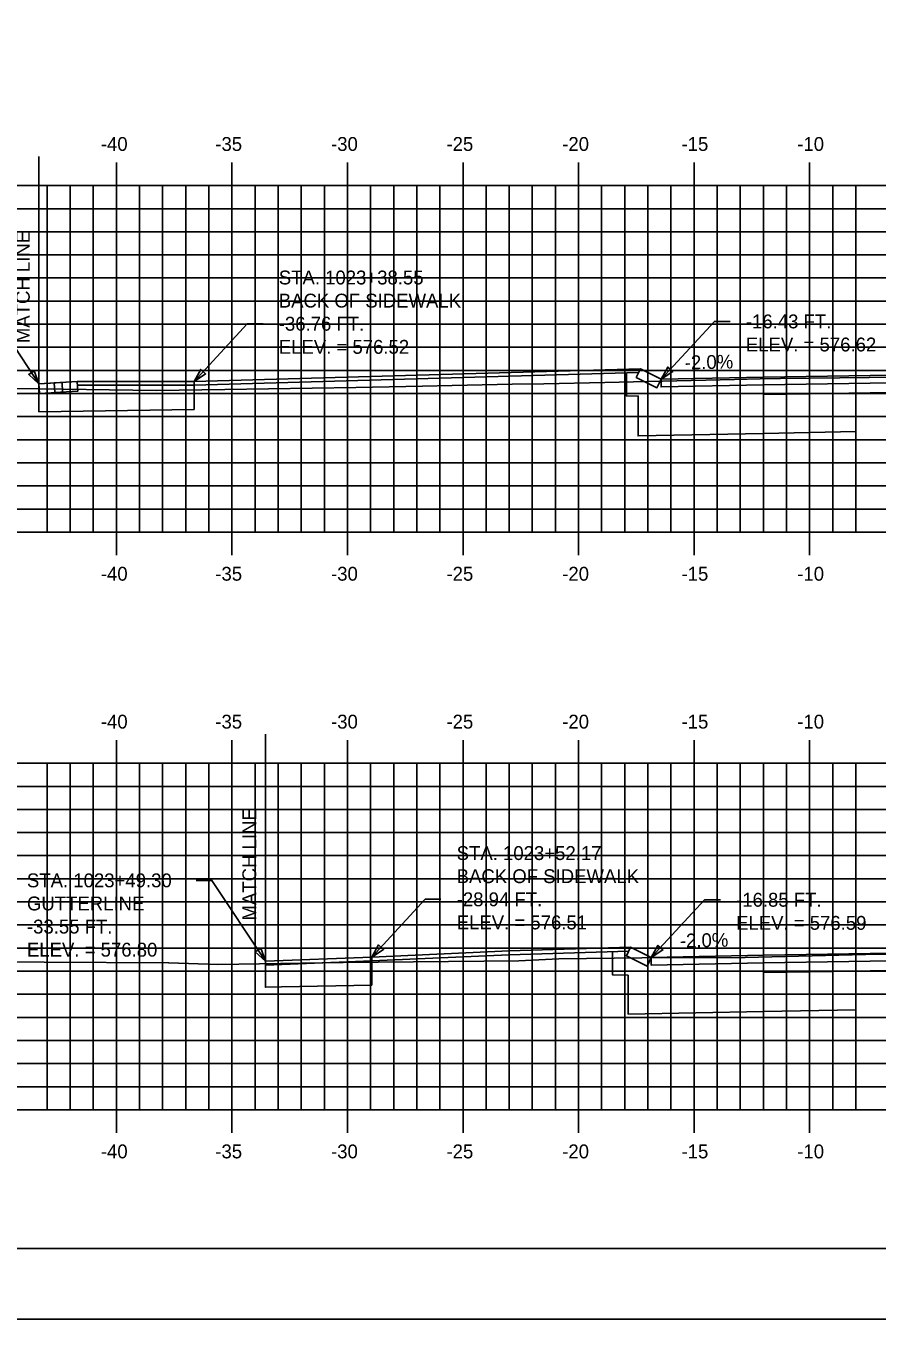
# Model space of a CAD drawing. Extents: x 1048565 to 1048735, y 781387 to 781497.
# Drawn here: x 1048604 to 1048640.8, y 781387.3 to 781443.3 of the extents above; entities that cross this region are included whole.
import ezdxf

# ---------------------------------------------------------------- set-up
doc = ezdxf.new("R2010")
doc.units = 0
for name, color, linetype in [('ANNOTATION', 7, 'Continuous'), ('BORDER', 7, 'Continuous'), ('D_Curb_Type_5_Lt', 7, 'Continuous'), ('D_Curb_Type_5_Rt', 7, 'Continuous'), ('D_Roadway_Edge_Shoulder', 7, 'Continuous'), ('D_Roadway_Edge_TW', 7, 'Continuous'), ('D_Roadway_Pavement', 7, 'Continuous'), ('D_Roadway_Sidewalks_Paved', 7, 'Continuous'), ('D_Roadway_SubGrade', 7, 'Continuous'), ('D_Text_Standard', 7, 'Continuous'), ('E_ROW_Line', 7, 'Continuous'), ('H_V ANNOTATION', 7, 'Continuous'), ('MAJOR', 7, 'Continuous'), ('MINOR', 7, 'Continuous'), ('PLOT BOUNDARY', 7, 'Continuous'), ('S_Roadway_Centerline', 7, 'Continuous')]:
    doc.layers.add(name, color=color, linetype=linetype)

msp = doc.modelspace()

# ---------------------------------------------------------------- linework, layer by layer
at = {"layer": 'ANNOTATION'}
for p, q in [((1048604.523, 781427.795), (1048604.523, 781426.585)), ((1048611.235, 781427.895), (1048611.235, 781426.685)), ((1048630.131, 781403.414), (1048624.876, 781403.256)), ((1048624.876, 781403.256), (1048618.935, 781402.985)), ((1048624.876, 781403.089), (1048618.935, 781402.819)), ((1048618.935, 781402.985), (1048618.935, 781401.775)), ((1048630.047, 781403.244), (1048624.876, 781403.089))]:
    msp.add_line(p, q, dxfattribs=at)
at = {"layer": 'BORDER'}
msp.add_lwpolyline([(1048572.876, 781390.375), (1048732.876, 781390.375), (1048732.876, 781495.375), (1048572.876, 781495.375)], close=True, dxfattribs=at)
at = {"layer": 'D_Curb_Type_5_Lt'}
for points in [[(1048630.556, 781428.444), (1048631.451, 781427.996), (1048631.265, 781427.624), (1048630.37, 781428.071)], [(1048630.131, 781403.414), (1048631.026, 781402.966), (1048630.84, 781402.594), (1048629.945, 781403.041)]]:
    msp.add_lwpolyline(points, close=True, dxfattribs=at)
at = {"layer": 'D_Curb_Type_5_Rt'}
for points in [[(1048604.523, 781427.795), (1048605.522, 781427.856), (1048605.547, 781427.44), (1048604.548, 781427.38)], [(1048605.187, 781427.835), (1048606.185, 781427.895), (1048606.21, 781427.48), (1048605.212, 781427.42)]]:
    msp.add_lwpolyline(points, close=True, dxfattribs=at)
at = {"layer": 'D_Roadway_Edge_Shoulder'}
for points in [[(1048635.876, 781428.085), (1048631.451, 781427.996), (1048631.451, 781427.663), (1048635.876, 781427.752)], [(1048635.876, 781403.063), (1048631.026, 781402.966), (1048631.026, 781402.633), (1048635.876, 781402.73)]]:
    msp.add_lwpolyline(points, close=True, dxfattribs=at)
at = {"layer": 'D_Roadway_Edge_TW'}
for points in [[(1048635.876, 781427.752), (1048635.876, 781428.085), (1048647.876, 781428.271), (1048659.876, 781428.3), (1048659.876, 781427.966), (1048647.876, 781427.938)], [(1048635.876, 781402.73), (1048635.876, 781403.063), (1048647.876, 781403.251), (1048659.876, 781403.385), (1048659.876, 781403.052), (1048647.876, 781402.918)]]:
    msp.add_lwpolyline(points, close=True, dxfattribs=at)
at = {"layer": 'D_Roadway_Pavement'}
for points in [[(1048635.876, 781427.335), (1048635.876, 781427.752), (1048647.876, 781427.938), (1048659.876, 781427.966), (1048659.876, 781427.55), (1048647.876, 781427.521)], [(1048635.876, 781402.314), (1048635.876, 781402.73), (1048647.876, 781402.918), (1048659.876, 781403.052), (1048659.876, 781402.636), (1048647.876, 781402.501)]]:
    msp.add_lwpolyline(points, close=True, dxfattribs=at)
at = {"layer": 'D_Roadway_Sidewalks_Paved'}
for p, q in [((1048611.235, 781427.895), (1048630.556, 781428.444)), ((1048630.474, 781428.279), (1048611.235, 781427.733)), ((1048604.523, 781427.795), (1048606.185, 781427.895)), ((1048606.185, 781427.895), (1048611.235, 781427.895)), ((1048611.235, 781427.733), (1048606.195, 781427.733)), ((1048614.327, 781402.805), (1048618.935, 781402.985)), ((1048614.327, 781402.639), (1048618.935, 781402.819))]:
    msp.add_line(p, q, dxfattribs=at)
at = {"layer": 'D_Roadway_SubGrade'}
for p, q in [((1048629.951, 781427.265), (1048629.951, 781428.264)), ((1048629.951, 781427.289), (1048629.951, 781427.265)), ((1048630.451, 781427.279), (1048629.951, 781427.265)), ((1048611.235, 781426.685), (1048604.523, 781426.585))]:
    msp.add_line(p, q, dxfattribs=at)
for points in [[(1048631.451, 781427.663), (1048635.876, 781427.752), (1048635.876, 781427.335), (1048639.876, 781427.397), (1048639.876, 781425.73), (1048635.876, 781425.65), (1048630.451, 781425.542), (1048630.451, 781427.279)], [(1048629.34, 781403.218), (1048629.34, 781402.218), (1048630.026, 781402.205)], [(1048629.34, 781403.218), (1048629.34, 781402.218), (1048630.026, 781402.205)], [(1048614.327, 781402.683), (1048614.327, 781402.639)], [(1048618.935, 781401.775), (1048615.026, 781401.697), (1048614.327, 781401.683), (1048614.327, 781402.683)], [(1048631.026, 781402.633), (1048635.876, 781402.73), (1048635.876, 781402.314), (1048639.876, 781402.376), (1048639.876, 781400.709), (1048635.876, 781400.629), (1048630.026, 781400.512), (1048630.026, 781402.205)]]:
    msp.add_lwpolyline(points, dxfattribs=at)
at = {"layer": 'D_Text_Standard'}
for points in [[(1048604.524, 781427.794), (1048602.206, 781431.294), (1048601.526, 781431.294)], [(1048611.235, 781427.895), (1048613.542, 781430.395), (1048614.222, 781430.395)], [(1048631.451, 781427.996), (1048633.757, 781430.496), (1048634.437, 781430.496)], [(1048614.327, 781402.805), (1048612.01, 781406.305), (1048611.33, 781406.305)], [(1048618.935, 781402.985), (1048621.242, 781405.485), (1048621.922, 781405.485)], [(1048631.026, 781402.966), (1048633.333, 781405.466), (1048634.013, 781405.466)]]:
    msp.add_lwpolyline(points, dxfattribs=at)
for points in [[(1048604.524, 781427.794), (1048604.081, 781428.199), (1048604.324, 781428.359)], [(1048611.235, 781427.895), (1048611.523, 781428.422), (1048611.737, 781428.225)], [(1048631.451, 781427.996), (1048631.739, 781428.523), (1048631.953, 781428.326)], [(1048618.935, 781402.985), (1048619.223, 781403.512), (1048619.437, 781403.315)], [(1048631.026, 781402.966), (1048631.314, 781403.493), (1048631.528, 781403.296)], [(1048614.327, 781402.805), (1048613.884, 781403.21), (1048614.127, 781403.371)]]:
    msp.add_lwpolyline(points, close=True, dxfattribs=at)
at = {"layer": 'E_ROW_Line'}
for p, q in [((1048604.524, 781427.627), (1048604.524, 781437.627)), ((1048614.327, 781402.639), (1048614.327, 781412.639))]:
    msp.add_line(p, q, dxfattribs=at)
at = {"layer": 'MAJOR'}
for p, q in [((1048607.876, 781437.377), (1048607.876, 781436.375)), ((1048612.876, 781437.377), (1048612.876, 781436.375)), ((1048617.876, 781437.377), (1048617.876, 781436.375)), ((1048622.876, 781437.377), (1048622.876, 781436.375)), ((1048627.876, 781437.377), (1048627.876, 781436.375)), ((1048632.876, 781437.377), (1048632.876, 781436.375)), ((1048637.876, 781437.377), (1048637.876, 781436.375)), ((1048577.876, 781436.375), (1048717.876, 781436.375)), ((1048577.876, 781436.375), (1048717.876, 781436.375)), ((1048607.876, 781421.375), (1048607.876, 781436.375)), ((1048612.876, 781421.375), (1048612.876, 781436.375)), ((1048617.876, 781421.375), (1048617.876, 781436.375)), ((1048622.876, 781421.375), (1048622.876, 781436.375)), ((1048627.876, 781421.375), (1048627.876, 781436.375)), ((1048632.876, 781421.375), (1048632.876, 781436.375)), ((1048637.876, 781421.375), (1048637.876, 781436.375)), ((1048577.876, 781431.375), (1048717.876, 781431.375)), ((1048577.876, 781426.375), (1048717.876, 781426.375)), ((1048577.876, 781421.375), (1048717.876, 781421.375)), ((1048577.876, 781421.375), (1048717.876, 781421.375)), ((1048607.876, 781420.373), (1048607.876, 781421.375)), ((1048612.876, 781420.373), (1048612.876, 781421.375)), ((1048617.876, 781420.373), (1048617.876, 781421.375)), ((1048622.876, 781420.373), (1048622.876, 781421.375)), ((1048627.876, 781420.373), (1048627.876, 781421.375)), ((1048632.876, 781420.373), (1048632.876, 781421.375)), ((1048637.876, 781420.373), (1048637.876, 781421.375)), ((1048607.876, 781412.377), (1048607.876, 781411.375)), ((1048612.876, 781412.377), (1048612.876, 781411.375)), ((1048617.876, 781412.377), (1048617.876, 781411.375)), ((1048622.876, 781412.377), (1048622.876, 781411.375)), ((1048627.876, 781412.377), (1048627.876, 781411.375)), ((1048632.876, 781412.377), (1048632.876, 781411.375)), ((1048637.876, 781412.377), (1048637.876, 781411.375)), ((1048577.876, 781411.375), (1048717.876, 781411.375)), ((1048577.876, 781411.375), (1048717.876, 781411.375)), ((1048607.876, 781396.375), (1048607.876, 781411.375)), ((1048612.876, 781396.375), (1048612.876, 781411.375)), ((1048617.876, 781396.375), (1048617.876, 781411.375)), ((1048622.876, 781396.375), (1048622.876, 781411.375)), ((1048627.876, 781396.375), (1048627.876, 781411.375)), ((1048632.876, 781396.375), (1048632.876, 781411.375)), ((1048637.876, 781396.375), (1048637.876, 781411.375)), ((1048577.876, 781406.375), (1048717.876, 781406.375)), ((1048577.876, 781401.375), (1048717.876, 781401.375)), ((1048577.876, 781396.375), (1048717.876, 781396.375)), ((1048577.876, 781396.375), (1048717.876, 781396.375)), ((1048607.876, 781395.373), (1048607.876, 781396.375)), ((1048612.876, 781395.373), (1048612.876, 781396.375)), ((1048617.876, 781395.373), (1048617.876, 781396.375)), ((1048622.876, 781395.373), (1048622.876, 781396.375)), ((1048627.876, 781395.373), (1048627.876, 781396.375)), ((1048632.876, 781395.373), (1048632.876, 781396.375)), ((1048637.876, 781395.373), (1048637.876, 781396.375))]:
    msp.add_line(p, q, dxfattribs=at)
at = {"layer": 'MINOR'}
for p, q in [((1048604.876, 781421.375), (1048604.876, 781436.375)), ((1048605.876, 781421.375), (1048605.876, 781436.375)), ((1048606.876, 781421.375), (1048606.876, 781436.375)), ((1048608.876, 781421.375), (1048608.876, 781436.375)), ((1048609.876, 781421.375), (1048609.876, 781436.375)), ((1048610.876, 781421.375), (1048610.876, 781436.375)), ((1048611.876, 781421.375), (1048611.876, 781436.375)), ((1048613.876, 781421.375), (1048613.876, 781436.375)), ((1048614.876, 781421.375), (1048614.876, 781436.375)), ((1048615.876, 781421.375), (1048615.876, 781436.375)), ((1048616.876, 781421.375), (1048616.876, 781436.375)), ((1048618.876, 781421.375), (1048618.876, 781436.375)), ((1048619.876, 781421.375), (1048619.876, 781436.375)), ((1048620.876, 781421.375), (1048620.876, 781436.375)), ((1048621.876, 781421.375), (1048621.876, 781436.375)), ((1048623.876, 781421.375), (1048623.876, 781436.375)), ((1048624.876, 781421.375), (1048624.876, 781436.375)), ((1048625.876, 781421.375), (1048625.876, 781436.375)), ((1048626.876, 781421.375), (1048626.876, 781436.375)), ((1048628.876, 781421.375), (1048628.876, 781436.375)), ((1048629.876, 781421.375), (1048629.876, 781436.375)), ((1048630.876, 781421.375), (1048630.876, 781436.375)), ((1048631.876, 781421.375), (1048631.876, 781436.375)), ((1048633.876, 781421.375), (1048633.876, 781436.375)), ((1048634.876, 781421.375), (1048634.876, 781436.375)), ((1048635.876, 781421.375), (1048635.876, 781436.375)), ((1048636.876, 781421.375), (1048636.876, 781436.375)), ((1048638.876, 781421.375), (1048638.876, 781436.375)), ((1048639.876, 781421.375), (1048639.876, 781436.375)), ((1048577.876, 781435.375), (1048717.876, 781435.375)), ((1048577.876, 781434.375), (1048717.876, 781434.375)), ((1048577.876, 781433.375), (1048717.876, 781433.375)), ((1048577.876, 781432.375), (1048717.876, 781432.375)), ((1048577.876, 781430.375), (1048717.876, 781430.375)), ((1048577.876, 781429.375), (1048717.876, 781429.375)), ((1048577.876, 781428.375), (1048717.876, 781428.375)), ((1048577.876, 781427.375), (1048717.876, 781427.375)), ((1048577.876, 781425.375), (1048717.876, 781425.375)), ((1048577.876, 781424.375), (1048717.876, 781424.375)), ((1048577.876, 781423.375), (1048717.876, 781423.375)), ((1048577.876, 781422.375), (1048717.876, 781422.375)), ((1048604.876, 781396.375), (1048604.876, 781411.375)), ((1048605.876, 781396.375), (1048605.876, 781411.375)), ((1048606.876, 781396.375), (1048606.876, 781411.375)), ((1048608.876, 781396.375), (1048608.876, 781411.375)), ((1048609.876, 781396.375), (1048609.876, 781411.375)), ((1048610.876, 781396.375), (1048610.876, 781411.375)), ((1048611.876, 781396.375), (1048611.876, 781411.375)), ((1048613.876, 781396.375), (1048613.876, 781411.375)), ((1048614.876, 781396.375), (1048614.876, 781411.375)), ((1048615.876, 781396.375), (1048615.876, 781411.375)), ((1048616.876, 781396.375), (1048616.876, 781411.375)), ((1048618.876, 781396.375), (1048618.876, 781411.375)), ((1048619.876, 781396.375), (1048619.876, 781411.375)), ((1048620.876, 781396.375), (1048620.876, 781411.375)), ((1048621.876, 781396.375), (1048621.876, 781411.375)), ((1048623.876, 781396.375), (1048623.876, 781411.375)), ((1048624.876, 781396.375), (1048624.876, 781411.375)), ((1048625.876, 781396.375), (1048625.876, 781411.375)), ((1048626.876, 781396.375), (1048626.876, 781411.375)), ((1048628.876, 781396.375), (1048628.876, 781411.375)), ((1048629.876, 781396.375), (1048629.876, 781411.375)), ((1048630.876, 781396.375), (1048630.876, 781411.375)), ((1048631.876, 781396.375), (1048631.876, 781411.375)), ((1048633.876, 781396.375), (1048633.876, 781411.375)), ((1048634.876, 781396.375), (1048634.876, 781411.375)), ((1048635.876, 781396.375), (1048635.876, 781411.375)), ((1048636.876, 781396.375), (1048636.876, 781411.375)), ((1048638.876, 781396.375), (1048638.876, 781411.375)), ((1048639.876, 781396.375), (1048639.876, 781411.375)), ((1048577.876, 781410.375), (1048717.876, 781410.375)), ((1048577.876, 781409.375), (1048717.876, 781409.375)), ((1048577.876, 781408.375), (1048717.876, 781408.375)), ((1048577.876, 781407.375), (1048717.876, 781407.375)), ((1048577.876, 781405.375), (1048717.876, 781405.375)), ((1048577.876, 781404.375), (1048717.876, 781404.375)), ((1048577.876, 781403.375), (1048717.876, 781403.375)), ((1048577.876, 781402.375), (1048717.876, 781402.375)), ((1048577.876, 781400.375), (1048717.876, 781400.375)), ((1048577.876, 781399.375), (1048717.876, 781399.375)), ((1048577.876, 781398.375), (1048717.876, 781398.375)), ((1048577.876, 781397.375), (1048717.876, 781397.375))]:
    msp.add_line(p, q, dxfattribs=at)
at = {"layer": 'PLOT BOUNDARY'}
msp.add_lwpolyline([(1048564.783, 781387.316), (1048734.783, 781387.316), (1048734.783, 781497.316), (1048564.783, 781497.316)], close=True, dxfattribs=at)
at = {"layer": 'S_Roadway_Centerline'}
for points in [[(1048603.553, 781427.592), (1048609.595, 781427.511), (1048612.565, 781427.554), (1048618.245, 781427.637), (1048621.117, 781427.687), (1048622.407, 781427.72), (1048625.009, 781427.781), (1048626.379, 781427.798), (1048629.011, 781427.846), (1048634.632, 781427.977), (1048635.74, 781428.013), (1048636.618, 781428.019), (1048648.138, 781428.155), (1048656.906, 781428.049), (1048661.788, 781428.023), (1048665.69, 781427.845), (1048666.193, 781427.839), (1048666.299, 781427.959), (1048666.665, 781428.409), (1048668.971, 781428.316), (1048669.378, 781427.97), (1048675.683, 781428.333)], [(1048599.349, 781402.799), (1048610.135, 781402.743), (1048610.142, 781402.743), (1048612.266, 781402.671), (1048617.687, 781402.752), (1048625.292, 781402.828), (1048627.022, 781402.905), (1048630.608, 781402.949), (1048635.094, 781402.972), (1048640.296, 781403.09), (1048648.215, 781403.183), (1048658.124, 781403.062), (1048661.819, 781402.987), (1048665.783, 781402.694), (1048666.704, 781402.682), (1048667.556, 781402.811), (1048668.005, 781403.321), (1048668.113, 781403.15), (1048670.427, 781403.069), (1048678.84, 781403.52)]]:
    msp.add_lwpolyline(points, dxfattribs=at)

# ---------------------------------------------------------------- texts
at = {"layer": 'ANNOTATION'}
for p in [(1048632.478, 781428.417), (1048632.266, 781403.392)]:
    msp.add_text('-2.0%', height=0.6, rotation=1.1458, dxfattribs=at).set_placement(p)
at = {"layer": 'D_Text_Standard'}
for s, p in [('STA. 1023+38.55', (1048614.902, 781432.096)), ('BACK OF SIDEWALK', (1048614.902, 781431.096)), ('-36.76 FT.', (1048614.902, 781430.095)), ('-16.43 FT.', (1048635.117, 781430.196)), ('ELEV. = 576.52', (1048614.902, 781429.095)), ('ELEV. = 576.62', (1048635.117, 781429.196)), ('STA. 1023+52.17', (1048622.602, 781407.186)), ('BACK OF SIDEWALK', (1048622.602, 781406.186)), ('STA. 1023+49.30', (1048604.004, 781406.005)), ('-28.94 FT.', (1048622.602, 781405.185)), ('-16.85 FT.', (1048634.693, 781405.166)), ('GUTTERLINE', (1048604.004, 781405.005)), ('-33.55 FT.', (1048604.004, 781404.005)), ('ELEV. = 576.51', (1048622.602, 781404.185)), ('ELEV. = 576.59', (1048634.693, 781404.166)), ('ELEV. = 576.80', (1048604.004, 781403.005))]:
    msp.add_text(s, height=0.6, dxfattribs=at).set_placement(p)
at = {"layer": 'E_ROW_Line'}
for p in [(1048604.124, 781429.555), (1048613.927, 781404.567)]:
    msp.add_text('MATCH LINE', height=0.6, rotation=90, dxfattribs=at).set_placement(p)
at = {"layer": 'H_V ANNOTATION'}
for s, p in [('-40', (1048607.202, 781437.875)), ('-35', (1048612.156, 781437.875)), ('-30', (1048617.164, 781437.875)), ('-25', (1048622.161, 781437.875)), ('-20', (1048627.169, 781437.875)), ('-15', (1048632.333, 781437.875)), ('-10', (1048637.341, 781437.875)), ('-40', (1048607.202, 781419.275)), ('-35', (1048612.156, 781419.275)), ('-30', (1048617.164, 781419.275)), ('-25', (1048622.161, 781419.275)), ('-20', (1048627.169, 781419.275)), ('-15', (1048632.333, 781419.275)), ('-10', (1048637.341, 781419.275)), ('-40', (1048607.202, 781412.875)), ('-35', (1048612.156, 781412.875)), ('-30', (1048617.164, 781412.875)), ('-25', (1048622.161, 781412.875)), ('-20', (1048627.169, 781412.875)), ('-15', (1048632.333, 781412.875)), ('-10', (1048637.341, 781412.875)), ('-40', (1048607.202, 781394.275)), ('-35', (1048612.156, 781394.275)), ('-30', (1048617.164, 781394.275)), ('-25', (1048622.161, 781394.275)), ('-20', (1048627.169, 781394.275)), ('-15', (1048632.333, 781394.275)), ('-10', (1048637.341, 781394.275))]:
    msp.add_text(s, height=0.6, dxfattribs=at).set_placement(p)

doc.saveas('drawing.dxf')
